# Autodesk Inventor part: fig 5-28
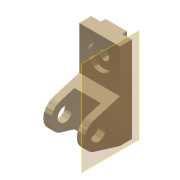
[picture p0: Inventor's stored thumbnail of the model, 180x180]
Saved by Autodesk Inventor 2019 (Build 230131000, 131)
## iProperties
Shininess: 65.0
Angle Display Precision: 2
Document Length Units: 11269
Document Angle Units: 11279
Document Time Units: 11290
Document Mass Units: 11283
Document Length Units Precision: 3
Document Angle Units Precision: 2
Created: 2001-11
Part Number: fig 5-28
Document SubType Name: Modeling
Designer: Renu Muthoo
Density: 1 g/cm^3
Material: Generic
Appearance: Metal-Titanium (Polished)
Density: 0.0
Volumn: 0.0
Area: 0.0
PropertySet Name: Model Information
Control State: 0
Master: False
Checked Out: False
Author: Renu Muthoo
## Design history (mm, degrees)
node "Sketch1"
sketch "Sketch2"
  geometry: L1 (33.257, 104.664)-(33.257, -75.336); L2 (33.257, -75.336)-(8.257, -75.336); L3 (8.257, -75.336)-(-45.451, -59.045); L4 (-45.451, -1.628)-(8.257, 14.664); L5 (8.257, 14.664)-(8.257, 104.664); L6 (8.257, 104.664)-(33.257, 104.664); C1 r 15 at (-36.743, -30.336); A1 r 30 centre (-36.743, -30.336) between (-45.451, -1.628) and (-45.451, -59.045)
  constraints: 12 end point, 2 centre point, 2 equal length, 2 parallel, 2 point on circle, 2 tangent, 1 coincident, 1 perpendicular, 1 vertical
  dimensions: "d0" = 180 distance of L1.start L1.end; "d1" = 30 radius of A1; "d2" = 25 distance of L5.end L1.start; "d3" = 45 distance from line of L2 A1.centre; "d4" = 70 distance from line of L1 A1.centre; "d5" = 30 diameter of C1
extrude "Extrusion1" new body sketch "Sketch2" distance "d6" = 85; taper "d7" = 0 deg
workplane "Work Plane1"
sketch "Sketch3"
  geometry: L1 (15, 62.364)-(70, 62.364); L2 (70, 62.364)-(70, -52.386); L3 (70, -52.386)-(15, -52.386); L4 (15, -52.386)-(15, 62.364); L5 (0, -45)-(0, -28.708) reference
  constraints: 8 end point, 2 parallel, 1 horizontal, 1 perpendicular
  dimensions: "d8" = 55 distance of L1.start L1.end; "d9" = 15 distance between parallel lines of L5 L4
extrude "Extrusion2" cut sketch "Sketch3" distance "d10" = 50; taper "d11" = 0 deg
sketch "Sketch4"
  geometry: L1 (0, 25)-(85, 25) reference; L2 (0, 0)-(0, 25) reference; L3 (20, 25)-(65, 25); L4 (65, 25)-(65, 35); L5 (65, 35)-(20, 35); L6 (20, 35)-(20, 25)
  constraints: 8 end point, 2 parallel, 1 horizontal, 1 perpendicular, 1 point on line
  dimensions: "d12" = 45 distance of L4.end L5.end; "d13" = 10 distance of L3.end L4.end; "d14" = 20 distance between parallel lines of L2 L6
extrude "Extrusion3" join sketch "Sketch4" stored distance "d15" = 50; taper "d16" = 0 deg
sketch "Sketch5"
  geometry: L1 (85, 0)-(85, 90) reference; L2 (0, 90)-(85, 90) reference; 1 further point
  dimensions: "d17" = 42 distance from line of L2 point (42.5, 48); "d18" = 42.5 distance from line of L1 point (42.5, 48)
hole "Hole1" sketch "Sketch5" at (42.5, 48) diameter "d19" = 20; stored, may be unused: countersink angle "d23" = 82 deg, drill point angle "d25" = 118 deg; dims "d20" = 6, "d21" = 50, "d22" = 10, "d24" = 8
workplane "Work Plane4"
body "Solid1"
other parameters: "d26" = 0
